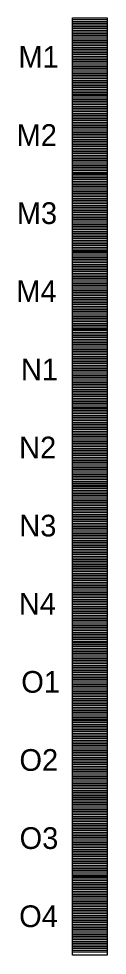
# Model space of a CAD drawing. Extents: x -124 to 80, y -10800 to 19.
# Drawn here: x -124 to 80, y -10800 to -8642 of the extents above; entities that cross this region are included whole.
import ezdxf

# ---------------------------------------------------------------- set-up
doc = ezdxf.new("R2010")
doc.units = 0
for name, color, linetype in [('Scratch_Level_1', 7, 'Continuous'), ('Scratch_Level_3', 7, 'Continuous'), ('Sheet Clip Boundary CELL', 7, 'Continuous')]:
    doc.layers.add(name, color=color, linetype=linetype)

msp = doc.modelspace()

# ---------------------------------------------------------------- linework, layer by layer
at = {"layer": 'Scratch_Level_1'}
for p, q in [((0, -8644), (80, -8644)), ((0, -8648), (80, -8648)), ((0, -8652), (80, -8652)), ((0, -8656), (80, -8656)), ((0, -8660), (80, -8660)), ((0, -8664), (80, -8664)), ((0, -8668), (80, -8668)), ((0, -8672), (80, -8672)), ((0, -8676), (80, -8676)), ((0, -8680), (80, -8680)), ((0, -8684), (80, -8684)), ((0, -8688), (80, -8688)), ((0, -8692), (80, -8692)), ((0, -8696), (80, -8696)), ((0, -8700), (80, -8700)), ((0, -8704), (80, -8704)), ((0, -8708), (80, -8708)), ((0, -8712), (80, -8712)), ((0, -8716), (80, -8716)), ((0, -8720), (80, -8720)), ((0, -8724), (80, -8724)), ((0, -8728), (80, -8728)), ((0, -8732), (80, -8732)), ((0, -8736), (80, -8736)), ((0, -8740), (80, -8740)), ((0, -8744), (80, -8744)), ((0, -8748), (80, -8748)), ((0, -8752), (80, -8752)), ((0, -8756), (80, -8756)), ((0, -8760), (80, -8760)), ((0, -8764), (80, -8764)), ((0, -8768), (80, -8768)), ((0, -8772), (80, -8772)), ((0, -8776), (80, -8776)), ((0, -8780), (80, -8780)), ((0, -8784), (80, -8784)), ((0, -8788), (80, -8788)), ((0, -8792), (80, -8792)), ((0, -8796), (80, -8796)), ((0, -8800), (80, -8800)), ((0, -8804), (80, -8804)), ((0, -8808), (80, -8808)), ((0, -8812), (80, -8812)), ((0, -8812), (80, -8812)), ((0, -8816), (80, -8816)), ((0, -8820), (80, -8820)), ((0, -8824), (80, -8824)), ((0, -8828), (80, -8828)), ((0, -8832), (80, -8832)), ((0, -8836), (80, -8836)), ((0, -8840), (80, -8840)), ((0, -8844), (80, -8844)), ((0, -8848), (80, -8848)), ((0, -8852), (80, -8852)), ((0, -8856), (80, -8856)), ((0, -8860), (80, -8860)), ((0, -8864), (80, -8864)), ((0, -8868), (80, -8868)), ((0, -8872), (80, -8872)), ((0, -8876), (80, -8876)), ((0, -8880), (80, -8880)), ((0, -8884), (80, -8884)), ((0, -8888), (80, -8888)), ((0, -8892), (80, -8892)), ((0, -8896), (80, -8896)), ((0, -8900), (80, -8900)), ((0, -8904), (80, -8904)), ((0, -8908), (80, -8908)), ((0, -8912), (80, -8912)), ((0, -8916), (80, -8916)), ((0, -8920), (80, -8920)), ((0, -8924), (80, -8924)), ((0, -8928), (80, -8928)), ((0, -8932), (80, -8932)), ((0, -8936), (80, -8936)), ((0, -8940), (80, -8940)), ((0, -8944), (80, -8944)), ((0, -8948), (80, -8948)), ((0, -8952), (80, -8952)), ((0, -8956), (80, -8956)), ((0, -8960), (80, -8960)), ((0, -8964), (80, -8964)), ((0, -8968), (80, -8968)), ((0, -8972), (80, -8972)), ((0, -8976), (80, -8976)), ((0, -8980), (80, -8980)), ((0, -8984), (80, -8984)), ((0, -8988), (80, -8988)), ((0, -8992), (80, -8992)), ((0, -8992), (80, -8992)), ((0, -8996), (80, -8996)), ((0, -9000), (80, -9000)), ((0, -9004), (80, -9004)), ((0, -9008), (80, -9008)), ((0, -9012), (80, -9012)), ((0, -9016), (80, -9016)), ((0, -9020), (80, -9020)), ((0, -9024), (80, -9024)), ((0, -9028), (80, -9028)), ((0, -9032), (80, -9032)), ((0, -9036), (80, -9036)), ((0, -9040), (80, -9040)), ((0, -9044), (80, -9044)), ((0, -9048), (80, -9048)), ((0, -9052), (80, -9052)), ((0, -9056), (80, -9056)), ((0, -9060), (80, -9060)), ((0, -9064), (80, -9064)), ((0, -9068), (80, -9068)), ((0, -9072), (80, -9072)), ((0, -9076), (80, -9076)), ((0, -9080), (80, -9080)), ((0, -9084), (80, -9084)), ((0, -9088), (80, -9088)), ((0, -9092), (80, -9092)), ((0, -9096), (80, -9096)), ((0, -9100), (80, -9100)), ((0, -9104), (80, -9104)), ((0, -9108), (80, -9108)), ((0, -9112), (80, -9112)), ((0, -9116), (80, -9116)), ((0, -9120), (80, -9120)), ((0, -9124), (80, -9124)), ((0, -9128), (80, -9128)), ((0, -9132), (80, -9132)), ((0, -9136), (80, -9136)), ((0, -9140), (80, -9140)), ((0, -9144), (80, -9144)), ((0, -9148), (80, -9148)), ((0, -9152), (80, -9152)), ((0, -9156), (80, -9156)), ((0, -9160), (80, -9160)), ((0, -9164), (80, -9164)), ((0, -9168), (80, -9168)), ((0, -9172), (80, -9172)), ((0, -9172), (80, -9172)), ((0, -9176), (80, -9176)), ((0, -9180), (80, -9180)), ((0, -9184), (80, -9184)), ((0, -9188), (80, -9188)), ((0, -9192), (80, -9192)), ((0, -9196), (80, -9196)), ((0, -9200), (80, -9200)), ((0, -9204), (80, -9204)), ((0, -9208), (80, -9208)), ((0, -9212), (80, -9212)), ((0, -9216), (80, -9216)), ((0, -9220), (80, -9220)), ((0, -9224), (80, -9224)), ((0, -9228), (80, -9228)), ((0, -9232), (80, -9232)), ((0, -9236), (80, -9236)), ((0, -9240), (80, -9240)), ((0, -9244), (80, -9244)), ((0, -9248), (80, -9248)), ((0, -9252), (80, -9252)), ((0, -9256), (80, -9256)), ((0, -9260), (80, -9260)), ((0, -9264), (80, -9264)), ((0, -9268), (80, -9268)), ((0, -9272), (80, -9272)), ((0, -9276), (80, -9276)), ((0, -9280), (80, -9280)), ((0, -9284), (80, -9284)), ((0, -9288), (80, -9288)), ((0, -9292), (80, -9292)), ((0, -9296), (80, -9296)), ((0, -9300), (80, -9300)), ((0, -9304), (80, -9304)), ((0, -9308), (80, -9308)), ((0, -9312), (80, -9312)), ((0, -9316), (80, -9316)), ((0, -9320), (80, -9320)), ((0, -9324), (80, -9324)), ((0, -9328), (80, -9328)), ((0, -9332), (80, -9332)), ((0, -9336), (80, -9336)), ((0, -9340), (80, -9340)), ((0, -9344), (80, -9344)), ((0, -9348), (80, -9348)), ((0, -9352), (80, -9352)), ((0, -9352), (80, -9352)), ((0, -9352), (80, -9352)), ((0, -9356), (80, -9356)), ((0, -9360), (80, -9360)), ((0, -9364), (80, -9364)), ((0, -9368), (80, -9368)), ((0, -9372), (80, -9372)), ((0, -9376), (80, -9376)), ((0, -9380), (80, -9380)), ((0, -9384), (80, -9384)), ((0, -9388), (80, -9388)), ((0, -9392), (80, -9392)), ((0, -9396), (80, -9396)), ((0, -9400), (80, -9400)), ((0, -9404), (80, -9404)), ((0, -9408), (80, -9408)), ((0, -9412), (80, -9412)), ((0, -9416), (80, -9416)), ((0, -9420), (80, -9420)), ((0, -9424), (80, -9424)), ((0, -9428), (80, -9428)), ((0, -9432), (80, -9432)), ((0, -9436), (80, -9436)), ((0, -9440), (80, -9440)), ((0, -9444), (80, -9444)), ((0, -9448), (80, -9448)), ((0, -9452), (80, -9452)), ((0, -9456), (80, -9456)), ((0, -9460), (80, -9460)), ((0, -9464), (80, -9464)), ((0, -9468), (80, -9468)), ((0, -9472), (80, -9472)), ((0, -9476), (80, -9476)), ((0, -9480), (80, -9480)), ((0, -9484), (80, -9484)), ((0, -9488), (80, -9488)), ((0, -9492), (80, -9492)), ((0, -9496), (80, -9496)), ((0, -9500), (80, -9500)), ((0, -9504), (80, -9504)), ((0, -9508), (80, -9508)), ((0, -9512), (80, -9512)), ((0, -9516), (80, -9516)), ((0, -9520), (80, -9520)), ((0, -9524), (80, -9524)), ((0, -9528), (80, -9528)), ((0, -9532), (80, -9532)), ((0, -9532), (80, -9532)), ((0, -9532), (80, -9532)), ((0, -9532), (80, -9532)), ((0, -9536), (80, -9536)), ((0, -9540), (80, -9540)), ((0, -9544), (80, -9544)), ((0, -9548), (80, -9548)), ((0, -9552), (80, -9552)), ((0, -9556), (80, -9556)), ((0, -9560), (80, -9560)), ((0, -9564), (80, -9564)), ((0, -9568), (80, -9568)), ((0, -9572), (80, -9572)), ((0, -9576), (80, -9576)), ((0, -9580), (80, -9580)), ((0, -9584), (80, -9584)), ((0, -9588), (80, -9588)), ((0, -9592), (80, -9592)), ((0, -9596), (80, -9596)), ((0, -9600), (80, -9600)), ((0, -9604), (80, -9604)), ((0, -9608), (80, -9608)), ((0, -9612), (80, -9612)), ((0, -9616), (80, -9616)), ((0, -9620), (80, -9620)), ((0, -9624), (80, -9624)), ((0, -9628), (80, -9628)), ((0, -9632), (80, -9632)), ((0, -9636), (80, -9636)), ((0, -9640), (80, -9640)), ((0, -9644), (80, -9644)), ((0, -9648), (80, -9648)), ((0, -9652), (80, -9652)), ((0, -9656), (80, -9656)), ((0, -9660), (80, -9660)), ((0, -9664), (80, -9664)), ((0, -9668), (80, -9668)), ((0, -9672), (80, -9672)), ((0, -9676), (80, -9676)), ((0, -9680), (80, -9680)), ((0, -9684), (80, -9684)), ((0, -9688), (80, -9688)), ((0, -9692), (80, -9692)), ((0, -9696), (80, -9696)), ((0, -9700), (80, -9700)), ((0, -9704), (80, -9704)), ((0, -9708), (80, -9708)), ((0, -9712), (80, -9712)), ((0, -9712), (80, -9712)), ((0, -9712), (80, -9712)), ((0, -9712), (80, -9712)), ((0, -9716), (80, -9716)), ((0, -9720), (80, -9720)), ((0, -9724), (80, -9724)), ((0, -9728), (80, -9728)), ((0, -9732), (80, -9732)), ((0, -9736), (80, -9736)), ((0, -9740), (80, -9740)), ((0, -9744), (80, -9744)), ((0, -9748), (80, -9748)), ((0, -9752), (80, -9752)), ((0, -9756), (80, -9756)), ((0, -9760), (80, -9760)), ((0, -9764), (80, -9764)), ((0, -9768), (80, -9768)), ((0, -9772), (80, -9772)), ((0, -9776), (80, -9776)), ((0, -9780), (80, -9780)), ((0, -9784), (80, -9784)), ((0, -9788), (80, -9788)), ((0, -9792), (80, -9792)), ((0, -9796), (80, -9796)), ((0, -9800), (80, -9800)), ((0, -9804), (80, -9804)), ((0, -9808), (80, -9808)), ((0, -9812), (80, -9812)), ((0, -9816), (80, -9816)), ((0, -9820), (80, -9820)), ((0, -9824), (80, -9824)), ((0, -9828), (80, -9828)), ((0, -9832), (80, -9832)), ((0, -9836), (80, -9836)), ((0, -9840), (80, -9840)), ((0, -9844), (80, -9844)), ((0, -9848), (80, -9848)), ((0, -9852), (80, -9852)), ((0, -9856), (80, -9856)), ((0, -9860), (80, -9860)), ((0, -9864), (80, -9864)), ((0, -9868), (80, -9868)), ((0, -9872), (80, -9872)), ((0, -9876), (80, -9876)), ((0, -9880), (80, -9880)), ((0, -9884), (80, -9884)), ((0, -9888), (80, -9888)), ((0, -9892), (80, -9892)), ((0, -9892), (80, -9892)), ((0, -9892), (80, -9892)), ((0, -9892), (80, -9892)), ((0, -9896), (80, -9896)), ((0, -9900), (80, -9900)), ((0, -9904), (80, -9904)), ((0, -9908), (80, -9908)), ((0, -9912), (80, -9912)), ((0, -9916), (80, -9916)), ((0, -9920), (80, -9920)), ((0, -9924), (80, -9924)), ((0, -9928), (80, -9928)), ((0, -9932), (80, -9932)), ((0, -9936), (80, -9936)), ((0, -9940), (80, -9940)), ((0, -9944), (80, -9944)), ((0, -9948), (80, -9948)), ((0, -9952), (80, -9952)), ((0, -9956), (80, -9956)), ((0, -9960), (80, -9960)), ((0, -9964), (80, -9964)), ((0, -9968), (80, -9968)), ((0, -9972), (80, -9972)), ((0, -9976), (80, -9976)), ((0, -9980), (80, -9980)), ((0, -9984), (80, -9984)), ((0, -9988), (80, -9988)), ((0, -9992), (80, -9992)), ((0, -9996), (80, -9996)), ((0, -10000), (80, -10000)), ((0, -10004), (80, -10004)), ((0, -10008), (80, -10008)), ((0, -10012), (80, -10012)), ((0, -10016), (80, -10016)), ((0, -10020), (80, -10020)), ((0, -10024), (80, -10024)), ((0, -10028), (80, -10028)), ((0, -10032), (80, -10032)), ((0, -10036), (80, -10036)), ((0, -10040), (80, -10040)), ((0, -10044), (80, -10044)), ((0, -10048), (80, -10048)), ((0, -10052), (80, -10052)), ((0, -10056), (80, -10056)), ((0, -10060), (80, -10060)), ((0, -10064), (80, -10064)), ((0, -10068), (80, -10068)), ((0, -10072), (80, -10072)), ((0, -10072), (80, -10072)), ((0, -10072), (80, -10072)), ((0, -10072), (80, -10072)), ((0, -10076), (80, -10076)), ((0, -10080), (80, -10080)), ((0, -10084), (80, -10084)), ((0, -10088), (80, -10088)), ((0, -10092), (80, -10092)), ((0, -10096), (80, -10096)), ((0, -10100), (80, -10100)), ((0, -10104), (80, -10104)), ((0, -10108), (80, -10108)), ((0, -10112), (80, -10112)), ((0, -10116), (80, -10116)), ((0, -10120), (80, -10120)), ((0, -10124), (80, -10124)), ((0, -10128), (80, -10128)), ((0, -10132), (80, -10132)), ((0, -10136), (80, -10136)), ((0, -10140), (80, -10140)), ((0, -10144), (80, -10144)), ((0, -10148), (80, -10148)), ((0, -10152), (80, -10152)), ((0, -10156), (80, -10156)), ((0, -10160), (80, -10160)), ((0, -10164), (80, -10164)), ((0, -10168), (80, -10168)), ((0, -10172), (80, -10172)), ((0, -10176), (80, -10176)), ((0, -10180), (80, -10180)), ((0, -10184), (80, -10184)), ((0, -10188), (80, -10188)), ((0, -10192), (80, -10192)), ((0, -10196), (80, -10196)), ((0, -10200), (80, -10200)), ((0, -10204), (80, -10204)), ((0, -10208), (80, -10208)), ((0, -10212), (80, -10212)), ((0, -10216), (80, -10216)), ((0, -10220), (80, -10220)), ((0, -10224), (80, -10224)), ((0, -10228), (80, -10228)), ((0, -10232), (80, -10232)), ((0, -10236), (80, -10236)), ((0, -10240), (80, -10240)), ((0, -10244), (80, -10244)), ((0, -10248), (80, -10248)), ((0, -10252), (80, -10252)), ((0, -10252), (80, -10252)), ((0, -10252), (80, -10252)), ((0, -10252), (80, -10252)), ((0, -10256), (80, -10256)), ((0, -10260), (80, -10260)), ((0, -10264), (80, -10264)), ((0, -10268), (80, -10268)), ((0, -10272), (80, -10272)), ((0, -10276), (80, -10276)), ((0, -10280), (80, -10280)), ((0, -10284), (80, -10284)), ((0, -10288), (80, -10288)), ((0, -10292), (80, -10292)), ((0, -10296), (80, -10296)), ((0, -10300), (80, -10300)), ((0, -10304), (80, -10304)), ((0, -10308), (80, -10308)), ((0, -10312), (80, -10312)), ((0, -10316), (80, -10316)), ((0, -10320), (80, -10320)), ((0, -10324), (80, -10324)), ((0, -10328), (80, -10328)), ((0, -10332), (80, -10332)), ((0, -10336), (80, -10336)), ((0, -10340), (80, -10340)), ((0, -10344), (80, -10344)), ((0, -10348), (80, -10348)), ((0, -10352), (80, -10352)), ((0, -10356), (80, -10356)), ((0, -10360), (80, -10360)), ((0, -10364), (80, -10364)), ((0, -10368), (80, -10368)), ((0, -10372), (80, -10372)), ((0, -10376), (80, -10376)), ((0, -10380), (80, -10380)), ((0, -10384), (80, -10384)), ((0, -10388), (80, -10388)), ((0, -10392), (80, -10392)), ((0, -10396), (80, -10396)), ((0, -10400), (80, -10400)), ((0, -10404), (80, -10404)), ((0, -10408), (80, -10408)), ((0, -10412), (80, -10412)), ((0, -10416), (80, -10416)), ((0, -10420), (80, -10420)), ((0, -10424), (80, -10424)), ((0, -10428), (80, -10428)), ((0, -10432), (80, -10432)), ((0, -10432), (80, -10432)), ((0, -10432), (80, -10432)), ((0, -10432), (80, -10432)), ((0, -10436), (80, -10436)), ((0, -10440), (80, -10440)), ((0, -10444), (80, -10444)), ((0, -10448), (80, -10448)), ((0, -10452), (80, -10452)), ((0, -10456), (80, -10456)), ((0, -10460), (80, -10460)), ((0, -10464), (80, -10464)), ((0, -10468), (80, -10468)), ((0, -10472), (80, -10472)), ((0, -10476), (80, -10476)), ((0, -10480), (80, -10480)), ((0, -10484), (80, -10484)), ((0, -10488), (80, -10488)), ((0, -10492), (80, -10492)), ((0, -10496), (80, -10496)), ((0, -10500), (80, -10500)), ((0, -10504), (80, -10504)), ((0, -10508), (80, -10508)), ((0, -10512), (80, -10512)), ((0, -10516), (80, -10516)), ((0, -10520), (80, -10520)), ((0, -10524), (80, -10524)), ((0, -10528), (80, -10528)), ((0, -10532), (80, -10532)), ((0, -10536), (80, -10536)), ((0, -10540), (80, -10540)), ((0, -10544), (80, -10544)), ((0, -10548), (80, -10548)), ((0, -10552), (80, -10552)), ((0, -10556), (80, -10556)), ((0, -10560), (80, -10560)), ((0, -10564), (80, -10564)), ((0, -10568), (80, -10568)), ((0, -10572), (80, -10572)), ((0, -10576), (80, -10576)), ((0, -10580), (80, -10580)), ((0, -10584), (80, -10584)), ((0, -10588), (80, -10588)), ((0, -10592), (80, -10592)), ((0, -10596), (80, -10596)), ((0, -10600), (80, -10600)), ((0, -10604), (80, -10604)), ((0, -10608), (80, -10608)), ((0, -10612), (80, -10612)), ((0, -10612), (80, -10612)), ((0, -10612), (80, -10612)), ((0, -10612), (80, -10612)), ((0, -10616), (80, -10616)), ((0, -10620), (80, -10620)), ((0, -10624), (80, -10624)), ((0, -10628), (80, -10628)), ((0, -10632), (80, -10632)), ((0, -10636), (80, -10636)), ((0, -10640), (80, -10640)), ((0, -10644), (80, -10644)), ((0, -10648), (80, -10648)), ((0, -10652), (80, -10652)), ((0, -10656), (80, -10656)), ((0, -10660), (80, -10660)), ((0, -10664), (80, -10664)), ((0, -10668), (80, -10668)), ((0, -10672), (80, -10672)), ((0, -10676), (80, -10676)), ((0, -10680), (80, -10680)), ((0, -10684), (80, -10684)), ((0, -10688), (80, -10688)), ((0, -10692), (80, -10692)), ((0, -10696), (80, -10696)), ((0, -10700), (80, -10700)), ((0, -10704), (80, -10704)), ((0, -10708), (80, -10708)), ((0, -10712), (80, -10712)), ((0, -10716), (80, -10716)), ((0, -10720), (80, -10720)), ((0, -10724), (80, -10724)), ((0, -10728), (80, -10728)), ((0, -10732), (80, -10732)), ((0, -10736), (80, -10736)), ((0, -10740), (80, -10740)), ((0, -10744), (80, -10744)), ((0, -10748), (80, -10748)), ((0, -10752), (80, -10752)), ((0, -10756), (80, -10756)), ((0, -10760), (80, -10760)), ((0, -10764), (80, -10764)), ((0, -10768), (80, -10768)), ((0, -10772), (80, -10772)), ((0, -10776), (80, -10776)), ((0, -10780), (80, -10780)), ((0, -10784), (80, -10784)), ((0, -10788), (80, -10788)), ((0, -10792), (80, -10792)), ((0, -10792), (80, -10792)), ((0, -10792), (80, -10792)), ((0, -10792), (80, -10792))]:
    msp.add_line(p, q, dxfattribs=at)
at = {"layer": 'Sheet Clip Boundary CELL'}
for points in [[(0, -8640), (80, -8640), (80, -8820), (0, -8820)], [(0, -8820), (80, -8820), (80, -9000), (0, -9000)], [(0, -9000), (80, -9000), (80, -9180), (0, -9180)], [(0, -9180), (80, -9180), (80, -9360), (0, -9360)], [(0, -9360), (80, -9360), (80, -9540), (0, -9540)], [(0, -9540), (80, -9540), (80, -9720), (0, -9720)], [(0, -9720), (80, -9720), (80, -9900), (0, -9900)], [(0, -9900), (80, -9900), (80, -10080), (0, -10080)], [(0, -10080), (80, -10080), (80, -10260), (0, -10260)], [(0, -10260), (80, -10260), (80, -10440), (0, -10440)], [(0, -10440), (80, -10440), (80, -10620), (0, -10620)], [(0, -10620), (80, -10620), (80, -10800), (0, -10800)]]:
    msp.add_lwpolyline(points, close=True, dxfattribs=at)

# ---------------------------------------------------------------- texts
at = {"layer": 'Scratch_Level_3'}
for s, p in [('M1', (-124.7, -8755)), ('M2', (-128.9, -8935)), ('M3', (-128.5, -9115)), ('M4', (-129.5, -9295)), ('N1', (-119, -9475)), ('N2', (-123.2, -9655)), ('N3', (-122.8, -9835)), ('N4', (-123.8, -10015)), ('O1', (-118.2, -10195)), ('O2', (-122.4, -10375)), ('O3', (-122, -10555)), ('O4', (-123, -10735))]:
    msp.add_text(s, height=50, dxfattribs=at).set_placement(p)

doc.saveas('drawing.dxf')
